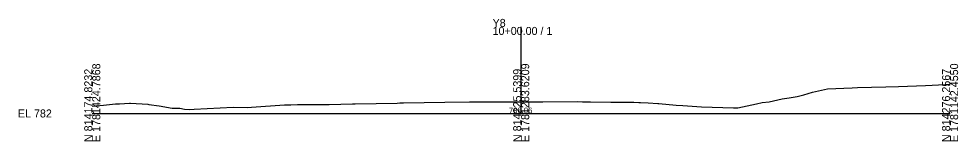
# Model space of a CAD drawing. Extents: x -26 to 303, y -10 to 5036.
# Drawn here: x -25.7 to 302.8, y -9.7 to 33.1 of the extents above; entities that cross this region are included whole.
import ezdxf

# ---------------------------------------------------------------- set-up
doc = ezdxf.new("R2010")
doc.units = 0
for name, color, linetype in [('Exist Cross Section Cell', 7, 'Continuous'), ('Exist XS Center Line Elevation Label', 7, 'Continuous'), ('Exist XS Ground Line', 7, 'Continuous')]:
    doc.layers.add(name, color=color, linetype=linetype)

msp = doc.modelspace()

# ---------------------------------------------------------------- linework, layer by layer
at = {"layer": 'Exist Cross Section Cell'}
for p, q in [((150, 0), (150, 30.23)), ((0, 0), (150, 0)), ((150, 0), (300, 0))]:
    msp.add_line(p, q, dxfattribs=at)
at = {"layer": 'Exist XS Ground Line'}
for p, q in [((291.39, 9.81), (298.28, 10.08)), ((298.28, 10.08), (300, 10.07)), ((248.89, 6.53), (251.87, 7.38)), ((251.87, 7.38), (257.11, 8.59)), ((257.11, 8.59), (265.73, 8.97)), ((265.73, 8.97), (267.59, 9.06)), ((267.59, 9.06), (272.47, 9.16)), ((272.47, 9.16), (277.49, 9.25)), ((277.49, 9.25), (281.98, 9.45)), ((281.98, 9.45), (291.39, 9.81)), ((3.95, 2.85), (8.11, 3.33)), ((8.11, 3.33), (9.48, 3.33)), ((9.48, 3.33), (13.03, 3.58)), ((13.03, 3.58), (13.37, 3.56)), ((13.37, 3.56), (19.45, 3.23)), ((82.83, 3.15), (91.06, 3.34)), ((91.06, 3.34), (91.98, 3.35)), ((91.98, 3.35), (106.58, 3.64)), ((106.58, 3.64), (107.58, 3.66)), ((107.58, 3.66), (108.31, 3.67)), ((108.31, 3.67), (108.89, 3.69)), ((108.89, 3.69), (123.34, 3.89)), ((123.34, 3.89), (131.96, 4.09)), ((131.96, 4.09), (134.38, 4.09)), ((134.38, 4.09), (150, 4.06)), ((150, 4.06), (150.39, 4.06)), ((150.39, 4.06), (157.57, 4.07)), ((157.57, 4.07), (169.54, 4.12)), ((169.54, 4.12), (171.42, 4.1)), ((171.42, 4.1), (171.8, 4.09)), ((171.8, 4.09), (172.53, 4.08)), ((172.53, 4.08), (174.22, 4.07)), ((174.22, 4.07), (181.3, 3.99)), ((181.3, 3.99), (188.69, 3.91)), ((188.69, 3.91), (189.44, 3.91)), ((189.44, 3.91), (191.14, 3.8)), ((191.14, 3.8), (191.76, 3.78)), ((191.76, 3.78), (194.39, 3.66)), ((194.39, 3.66), (197.85, 3.47)), ((197.85, 3.47), (198.2, 3.44)), ((198.2, 3.44), (204.17, 2.87)), ((225.78, 1.96), (232.33, 3.4)), ((232.33, 3.4), (234.32, 3.86)), ((234.32, 3.86), (236.75, 4.09)), ((236.75, 4.09), (241.23, 5.09)), ((241.23, 5.09), (243.68, 5.41)), ((243.68, 5.41), (246.48, 5.9)), ((246.48, 5.9), (248.89, 6.53)), ((0, 2.56), (3.95, 2.85)), ((19.45, 3.23), (19.75, 3.18)), ((19.75, 3.18), (23.4, 2.71)), ((23.4, 2.71), (27.9, 1.83)), ((27.9, 1.83), (30.62, 1.85)), ((30.62, 1.85), (32.24, 1.44)), ((32.24, 1.44), (33.86, 1.34)), ((33.86, 1.34), (35.59, 1.48)), ((35.59, 1.48), (49.23, 2.14)), ((49.23, 2.14), (54.24, 2.11)), ((54.24, 2.11), (55.72, 2.18)), ((55.72, 2.18), (67.27, 3)), ((67.27, 3), (69.45, 3.01)), ((69.45, 3.01), (71.75, 3.07)), ((71.75, 3.07), (78.91, 3.11)), ((78.91, 3.11), (80.64, 3.13)), ((80.64, 3.13), (82.83, 3.15)), ((204.17, 2.87), (206.49, 2.76)), ((206.49, 2.76), (213.12, 2.33)), ((213.12, 2.33), (224.3, 2.01)), ((224.3, 2.01), (224.74, 1.98)), ((224.74, 1.98), (225.78, 1.96))]:
    msp.add_line(p, q, dxfattribs=at)

# ---------------------------------------------------------------- texts
at = {"layer": 'Exist Cross Section Cell'}
for s, p in [('Y8', (140, 30.23)), ('10+00.00 / 1', (140, 27.43)), ('EL 782', (-26, -1.4))]:
    msp.add_text(s, height=2.8, dxfattribs=at).set_placement(p)
for s, p in [('E 1781424.7868', (2.8, -10)), ('E 1781283.6209', (152.8, -10)), ('E 1781142.4550', (302.8, -10)), ('N 814174.8232', (0, -10)), ('N 814225.5399', (150, -10)), ('N 814276.2567', (300, -10))]:
    msp.add_text(s, height=2.8, rotation=90, dxfattribs=at).set_placement(p)
at = {"layer": 'Exist XS Center Line Elevation Label'}
msp.add_text('786.06', height=2, dxfattribs=at).set_placement((145.73, 0.06))

doc.saveas('drawing.dxf')
